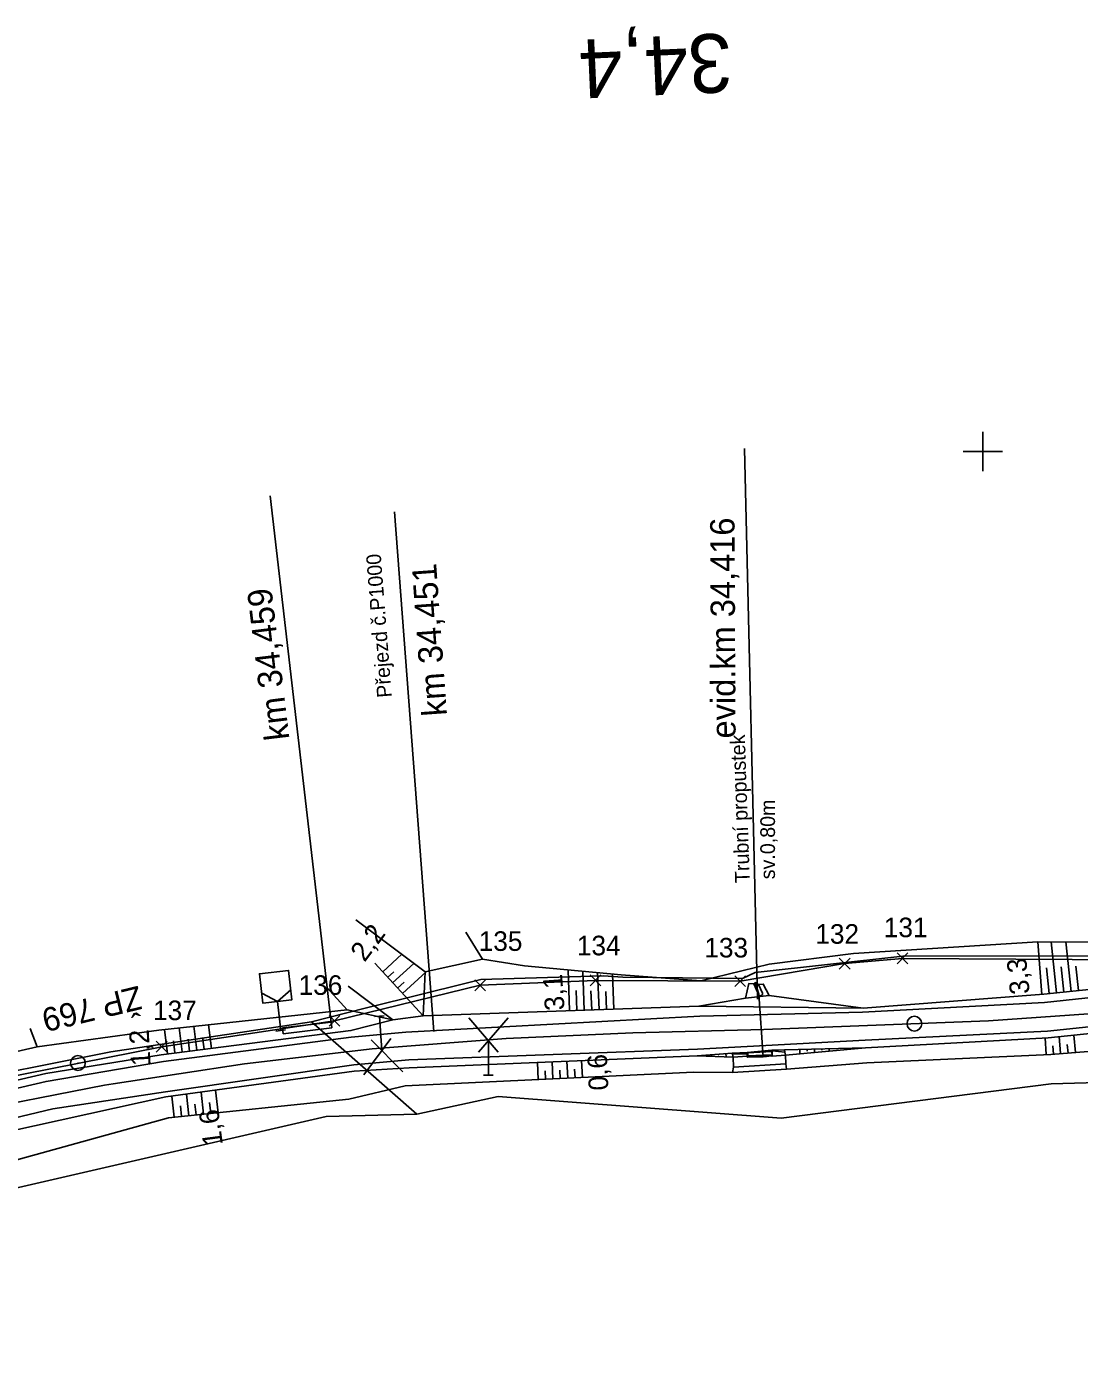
# Model space of a CAD drawing. Extents: x -805730 to -804640, y -1150889 to -1150366.
# Drawn here: x -805297.6 to -805190.1, y -1150691.7 to -1150556.6 of the extents above; entities that cross this region are included whole.
import ezdxf

# ---------------------------------------------------------------- set-up
doc = ezdxf.new("R2010")
doc.units = 0
for name, color, linetype in [('0381KM032-037P - Vrstva 1', 7, 'Continuous'), ('0381KM032-037P - Vrstva 17', 7, 'Continuous'), ('0381KM032-037P - Vrstva 19', 7, 'Continuous'), ('0381KM032-037P - Vrstva 4', 7, 'Continuous'), ('0381KM032-037P - Vrstva 48', 7, 'Continuous'), ('0381KM032-037P - Vrstva 49', 7, 'Continuous'), ('0381KM032-037P - Vrstva 51', 7, 'Continuous'), ('0381KM032-037P - Vrstva 55', 7, 'Continuous'), ('0381KM032-037P - Vrstva 7', 7, 'Continuous'), ('0381KM032-037P - Vrstva 9', 7, 'Continuous'), ('Default', 7, 'Continuous'), ('hran DP - hran DP', 7, 'Continuous'), ('krizky_1000 - Vrstva 1', 7, 'Continuous'), ('PSR_C2_2_Lomove_body_Vimperk - Vrstva 60', 7, 'Continuous'), ('PSR_C2_2_trasa_Vimperk - Kabelová trasa', 7, 'Continuous'), ('vyt_sit - ohrožené', 7, 'Continuous')]:
    doc.layers.add(name, color=color, linetype=linetype)

msp = doc.modelspace()

# ---------------------------------------------------------------- linework, layer by layer
at = {"layer": '0381KM032-037P - Vrstva 1'}
for points in [[(-805182.79, -1150656.72), (-805189.2, -1150657.4), (-805199.42, -1150658.12), (-805222.35, -1150659), (-805235.71, -1150659.34), (-805248.65, -1150659.92), (-805262.34, -1150660.99)], [(-805262.34, -1150660.99), (-805275.34, -1150662.5), (-805288.75, -1150664.54), (-805289.64, -1150664.68), (-805304.6, -1150667.62), (-805306.42, -1150668.06)]]:
    msp.add_lwpolyline(points, dxfattribs=at)
at = {"layer": '0381KM032-037P - Vrstva 17'}
for points in [[(-805070.8, -1150598.9), (-805121.06, -1150638.84), (-805152.76, -1150646.7), (-805170.92, -1150650.08), (-805194.39, -1150650.05), (-805213.2, -1150651.26), (-805221.79, -1150652.33), (-805228.79, -1150654.03)], [(-805228.79, -1150654.03), (-805236.91, -1150653.41), (-805246.77, -1150652.51), (-805251.08, -1150651.83), (-805252.77, -1150649.08)], [(-805266.94, -1150654.72), (-805264.88, -1150657), (-805284.09, -1150659.06), (-805296.52, -1150660.78), (-805297.22, -1150658.9)]]:
    msp.add_lwpolyline(points, dxfattribs=at)
at = {"layer": '0381KM032-037P - Vrstva 19'}
for p, q in [((-805224.33, -1150599.68), (-805223.01, -1150655.91)), ((-805222.9, -1150655.44), (-805223.36, -1150654.35)), ((-805222.89, -1150654.41), (-805222.49, -1150655.3)), ((-805223.99, -1150661.38), (-805221.54, -1150661.24)), ((-805221.51, -1150661.18), (-805221.49, -1150661.72)), ((-805225.47, -1150661.83), (-805224.04, -1150661.74)), ((-805224.04, -1150661.49), (-805224.04, -1150661.74)), ((-805221.51, -1150661.6), (-805224, -1150661.7)), ((-805224, -1150661.7), (-805224, -1150661.8)), ((-805224, -1150661.8), (-805221.51, -1150661.7)), ((-805221.51, -1150661.7), (-805221.51, -1150661.6))]:
    msp.add_line(p, q, dxfattribs=at)
msp.add_lwpolyline([(-805224.22, -1150655.82), (-805223.87, -1150654.3), (-805223.36, -1150654.35), (-805223.23, -1150654.21), (-805222.89, -1150654.41), (-805222.41, -1150654.36), (-805221.82, -1150655.55)], close=True, dxfattribs=at)
for points in [[(-805223.23, -1150654.21), (-805222.87, -1150655.41), (-805222.4, -1150661.78)], [(-805225.57, -1150661.42), (-805224.05, -1150661.35), (-805223.99, -1150661.38)], [(-805225.56, -1150661.53), (-805224.04, -1150661.49), (-805224.05, -1150661.35)], [(-805221.51, -1150661.7), (-805221.51, -1150661.69), (-805221.54, -1150661.24), (-805221.52, -1150661.12), (-805220.23, -1150661.07), (-805220.19, -1150661.33), (-805220.13, -1150661.62)], [(-805220.19, -1150661.33), (-805221.51, -1150661.18), (-805221.52, -1150661.12)], [(-805225.57, -1150661.42), (-805225.56, -1150661.53), (-805225.47, -1150661.83), (-805225.46, -1150662.84), (-805225.54, -1150663.4), (-805220.04, -1150663.05), (-805220.11, -1150662.52), (-805225.46, -1150662.84)], [(-805224, -1150661.7), (-805224.04, -1150661.74), (-805224.02, -1150661.84), (-805223.26, -1150661.81), (-805222.4, -1150661.78)], [(-805223.99, -1150661.81), (-805224, -1150661.8)], [(-805223.99, -1150661.38), (-805223.99, -1150661.81), (-805221.51, -1150661.69)], [(-805222.4, -1150661.78), (-805221.56, -1150661.7), (-805221.49, -1150661.72)], [(-805220.11, -1150662.52), (-805220.13, -1150661.62), (-805221.49, -1150661.72), (-805221.51, -1150661.6)]]:
    msp.add_lwpolyline(points, dxfattribs=at)
for centre, major_axis, ratio, start_param, end_param in [((-805222.69, -1150655.38), (0.215, 0.047), 0.800066, 3.235081, 6.495155), ((-805222.47, -1150661.77), (-0.4, -0.017), 0.197294, 3.17264, 6.315874), ((-805222.47, -1150661.77), (0.4, 0.019), 0.014453, 3.164337, 6.322931)]:
    msp.add_ellipse(centre, major_axis=major_axis, ratio=ratio, start_param=start_param, end_param=end_param, dxfattribs=at)
at = {"layer": '0381KM032-037P - Vrstva 4'}
for p, q in [((-805260.04, -1150606.16), (-805256.03, -1150659.22)), ((-805261.09, -1150657.61), (-805262.09, -1150657.68)), ((-805261.59, -1150657.65), (-805261.34, -1150661.14)), ((-805252.46, -1150657.82), (-805249.46, -1150661.32)), ((-805251.46, -1150661.32), (-805248.46, -1150657.82)), ((-805260.43, -1150659.92), (-805263.17, -1150663.62)), ((-805262.34, -1150660.99), (-805248.65, -1150659.92)), ((-805259.18, -1150663.34), (-805262.42, -1150660.06)), ((-805250.46, -1150663.67), (-805250.46, -1150660.17)), ((-805250.96, -1150663.67), (-805249.96, -1150663.67))]:
    msp.add_line(p, q, dxfattribs=at)
for points in [[(-805097.6, -1150634.39), (-805112.1, -1150639.75), (-805119.36, -1150642.27), (-805152.08, -1150650.89), (-805169.94, -1150653.7), (-805193.71, -1150656.24), (-805212.28, -1150657.22)], [(-805096.44, -1150637.01), (-805110.9, -1150642.46), (-805118.26, -1150644.98), (-805151.42, -1150653.61), (-805169.41, -1150656.67), (-805193.4, -1150659.17), (-805212.01, -1150660.08)], [(-805134.98, -1150644.55), (-805152.23, -1150649.93), (-805170.06, -1150652.94), (-805193.76, -1150655.4), (-805212.2, -1150656.84), (-805228.99, -1150656.61)], [(-805134.56, -1150650.98), (-805151.31, -1150654.12), (-805169.36, -1150657.36), (-805193.31, -1150659.84), (-805211.96, -1150660.88), (-805220.23, -1150661.07)], [(-805228.99, -1150656.61), (-805257.13, -1150657.62), (-805260.23, -1150658.03), (-805264.49, -1150659.11), (-805283.86, -1150661.58), (-805295.64, -1150663.5), (-805324.06, -1150670.09), (-805365.63, -1150680.4), (-805372.09, -1150681.89), (-805381.91, -1150683.24), (-805417.14, -1150687.42), (-805420, -1150686.97)], [(-805212.28, -1150657.22), (-805228.89, -1150657.63), (-805258.88, -1150659.27), (-805264.46, -1150659.8), (-805283.61, -1150662.28), (-805295.6, -1150664.3), (-805323.97, -1150670.91), (-805365.39, -1150681.52), (-805371.9, -1150683.14), (-805381.67, -1150685.01), (-805417.27, -1150688.09), (-805420, -1150686.97)], [(-805212.01, -1150660.08), (-805229.13, -1150661), (-805258.58, -1150662.1), (-805264.18, -1150662.62), (-805283.43, -1150665.36), (-805294.93, -1150667.11), (-805323.21, -1150673.86), (-805364.72, -1150684.28), (-805371.95, -1150685.67), (-805381.73, -1150687.49), (-805401.63, -1150689.36), (-805419.33, -1150691.07), (-805419.49, -1150691.68)], [(-805225.57, -1150661.42), (-805229.16, -1150661.68), (-805258.55, -1150662.93), (-805264.16, -1150663.27), (-805283.37, -1150665.88), (-805323.33, -1150674.68), (-805364.37, -1150685.33), (-805371.95, -1150687.26), (-805381.71, -1150688.97), (-805419.49, -1150691.68)]]:
    msp.add_lwpolyline(points, dxfattribs=at)
at = {"layer": '0381KM032-037P - Vrstva 48'}
for p, q in [((-805193.97, -1150655.42), (-805194.39, -1150650.05)), ((-805192.48, -1150655.27), (-805193.02, -1150650.05)), ((-805190.99, -1150655.11), (-805191.51, -1150650.05)), ((-805261.25, -1150653.12), (-805259.3, -1150651.33)), ((-805260.75, -1150653.68), (-805260.13, -1150653.11)), ((-805260.24, -1150654.23), (-805258.08, -1150652.25)), ((-805259.22, -1150655.33), (-805256.81, -1150653.11)), ((-805242.17, -1150657.08), (-805242.32, -1150652.92)), ((-805240.67, -1150657.03), (-805240.81, -1150653.06)), ((-805239.17, -1150656.98), (-805239.31, -1150653.2)), ((-805193.23, -1150655.34), (-805193.5, -1150652.7)), ((-805191.73, -1150655.19), (-805192, -1150652.62)), ((-805190.24, -1150655.03), (-805190.5, -1150652.54)), ((-805259.73, -1150654.78), (-805259.05, -1150654.16)), ((-805237.67, -1150656.92), (-805237.8, -1150653.33)), ((-805241.42, -1150657.06), (-805241.49, -1150655.02)), ((-805239.92, -1150657), (-805239.99, -1150655.06)), ((-805238.42, -1150656.95), (-805238.49, -1150655.11)), ((-805278.74, -1150660.93), (-805279.04, -1150658.52)), ((-805283.2, -1150661.49), (-805283.52, -1150659)), ((-805281.71, -1150661.3), (-805282.03, -1150658.84)), ((-805280.97, -1150661.21), (-805281.12, -1150659.98)), ((-805280.22, -1150661.11), (-805280.54, -1150658.68)), ((-805279.48, -1150661.02), (-805279.64, -1150659.81)), ((-805193.54, -1150661.57), (-805193.62, -1150659.86)), ((-805192.05, -1150661.47), (-805192.19, -1150659.72)), ((-805190.55, -1150661.35), (-805190.69, -1150659.57)), ((-805282.46, -1150661.4), (-805282.61, -1150660.16)), ((-805218.69, -1150661.03), (-805218.68, -1150661.49)), ((-805217.94, -1150661.02), (-805217.94, -1150661.22)), ((-805217.19, -1150661), (-805217.18, -1150661.35)), ((-805216.44, -1150660.98), (-805216.44, -1150661.13)), ((-805215.69, -1150660.96), (-805215.68, -1150661.22)), ((-805192.79, -1150661.53), (-805192.86, -1150660.66)), ((-805191.3, -1150661.41), (-805191.37, -1150660.53)), ((-805245.37, -1150664.11), (-805245.45, -1150662.37)), ((-805243.87, -1150664.03), (-805243.95, -1150662.31)), ((-805242.37, -1150663.96), (-805242.45, -1150662.25)), ((-805240.87, -1150663.89), (-805240.95, -1150662.18)), ((-805227.71, -1150661.57), (-805227.7, -1150661.74)), ((-805226.96, -1150661.52), (-805226.95, -1150661.64)), ((-805226.21, -1150661.47), (-805226.19, -1150661.8)), ((-805244.62, -1150664.07), (-805244.66, -1150663.21)), ((-805243.12, -1150664), (-805243.16, -1150663.14)), ((-805241.62, -1150663.93), (-805241.66, -1150663.07)), ((-805279.55, -1150667.65), (-805279.78, -1150665.39)), ((-805278.05, -1150667.5), (-805278.3, -1150665.19)), ((-805282.53, -1150667.97), (-805282.76, -1150665.8)), ((-805281.04, -1150667.81), (-805281.27, -1150665.6)), ((-805280.29, -1150667.73), (-805280.41, -1150666.61)), ((-805278.8, -1150667.58), (-805278.92, -1150666.44)), ((-805281.78, -1150667.89), (-805281.9, -1150666.79))]:
    msp.add_line(p, q, dxfattribs=at)
at = {"layer": '0381KM032-037P - Vrstva 49'}
for p, q in [((-805257.13, -1150657.62), (-805262.06, -1150652.24)), ((-805256.9, -1150653.13), (-805257.13, -1150657.62)), ((-805220.23, -1150661.07), (-805211.96, -1150660.88)), ((-805224.04, -1150661.74), (-805225.47, -1150661.83))]:
    msp.add_line(p, q, dxfattribs=at)
for points in [[(-805070.8, -1150598.9), (-805121.06, -1150638.84), (-805152.76, -1150646.7), (-805170.92, -1150650.08), (-805194.39, -1150650.05), (-805213.2, -1150651.26), (-805221.79, -1150652.33), (-805228.79, -1150654.03)], [(-805134.98, -1150644.55), (-805152.23, -1150649.93), (-805170.06, -1150652.94), (-805193.76, -1150655.4), (-805212.2, -1150656.84), (-805221.82, -1150655.55)], [(-805228.79, -1150654.03), (-805236.91, -1150653.41), (-805246.77, -1150652.51), (-805251.08, -1150651.83), (-805256.9, -1150653.13), (-805263.99, -1150647.81)], [(-805134.43, -1150652.2), (-805150.83, -1150656.03), (-805168.82, -1150659.61), (-805193.05, -1150661.55), (-805211.83, -1150662.42), (-805220.04, -1150663.05)], [(-805151.31, -1150654.12), (-805169.36, -1150657.36), (-805193.31, -1150659.84), (-805211.96, -1150660.88), (-805220.13, -1150661.62)], [(-805221.82, -1150655.55), (-805224.22, -1150655.82), (-805228.99, -1150656.61), (-805257.13, -1150657.62)], [(-805296.52, -1150660.78), (-805284.09, -1150659.06), (-805264.88, -1150657), (-805260.23, -1150658.03)], [(-805257.13, -1150657.62), (-805260.23, -1150658.03), (-805264.49, -1150659.11)], [(-805420, -1150686.97), (-805417.14, -1150687.42), (-805381.91, -1150683.24), (-805372.09, -1150681.89), (-805365.63, -1150680.4), (-805324.06, -1150670.09), (-805295.64, -1150663.5), (-805283.86, -1150661.58), (-805264.49, -1150659.11)], [(-805296.52, -1150660.78), (-805324.89, -1150667.28), (-805344.39, -1150673.21)], [(-805220.23, -1150661.07), (-805221.52, -1150661.12), (-805224.05, -1150661.35), (-805225.57, -1150661.42), (-805229.16, -1150661.68)], [(-805372.13, -1150688.5), (-805323.33, -1150674.68), (-805283.37, -1150665.88), (-805264.16, -1150663.27), (-805258.55, -1150662.93), (-805229.16, -1150661.68), (-805225.47, -1150661.83)], [(-805224.04, -1150661.74), (-805224.02, -1150661.84), (-805223.26, -1150661.81), (-805222.4, -1150661.78), (-805221.56, -1150661.7)], [(-805221.56, -1150661.7), (-805221.49, -1150661.72), (-805220.13, -1150661.62)], [(-805229.52, -1150663.36), (-805258.94, -1150664.75), (-805264.69, -1150666.1), (-805283.13, -1150668.03), (-805332.88, -1150681.81), (-805363.18, -1150690.85)], [(-805229.52, -1150663.36), (-805225.54, -1150663.4), (-805220.04, -1150663.05)]]:
    msp.add_lwpolyline(points, dxfattribs=at)
at = {"layer": '0381KM032-037P - Vrstva 51'}
msp.add_line((-805264.77, -1150654.58), (-805260.23, -1150658.03), dxfattribs=at)
msp.add_lwpolyline([(-805262.06, -1150652.24), (-805257.13, -1150657.62), (-805260.23, -1150658.03)], dxfattribs=at)
at = {"layer": '0381KM032-037P - Vrstva 55'}
msp.add_line((-805268.53, -1150658.22), (-805257.77, -1150667.64), dxfattribs=at)
at = {"layer": '0381KM032-037P - Vrstva 7'}
for p, q in [((-805272, -1150656.13), (-805271.65, -1150659.11)), ((-805272.15, -1150659.17), (-805271.16, -1150659.05))]:
    msp.add_line(p, q, dxfattribs=at)
for points in [[(-805272, -1150656.13), (-805270.51, -1150655.96), (-805270.85, -1150652.98), (-805273.83, -1150653.32), (-805273.49, -1150656.3), (-805272, -1150656.13)], [(-805273.6, -1150655.31), (-805272, -1150656.13), (-805270.62, -1150654.96)]]:
    msp.add_lwpolyline(points, dxfattribs=at)
msp.add_circle((-805206.98, -1150658.41), 0.75, dxfattribs=at)
at = {"layer": '0381KM032-037P - Vrstva 9'}
for p, q in [((-805266.48, -1150658.55), (-805272.73, -1150604.53)), ((-805266.52, -1150658.25), (-805271.48, -1150658.85)), ((-805266.52, -1150658.25), (-805266.59, -1150657.67)), ((-805266.45, -1150658.84), (-805266.52, -1150658.25)), ((-805271.48, -1150658.85), (-805271.41, -1150659.44)), ((-805271.41, -1150659.44), (-805266.45, -1150658.84))]:
    msp.add_line(p, q, dxfattribs=at)
at = {"layer": 'hran DP - hran DP'}
for p, q in [((-805223.22, -1150653.17), (-805208.17, -1150651.53)), ((-805208.17, -1150651.53), (-805178.93, -1150651.45)), ((-805224.51, -1150653.79), (-805223.22, -1150653.17)), ((-805259.03, -1150655.84), (-805251.25, -1150653.89)), ((-805251.25, -1150653.89), (-805238.75, -1150653.54)), ((-805238.75, -1150653.54), (-805236.73, -1150653.66)), ((-805236.73, -1150653.66), (-805224.51, -1150653.79)), ((-805263.04, -1150656.84), (-805259.03, -1150655.84)), ((-805268.53, -1150658.22), (-805263.04, -1150656.84)), ((-805288.99, -1150661.29), (-805268.53, -1150658.22)), ((-805313.93, -1150666.21), (-805288.99, -1150661.29)), ((-805161.69, -1150663.73), (-805193.03, -1150664.54)), ((-805193.03, -1150664.54), (-805220.59, -1150668.04)), ((-805249.45, -1150665.86), (-805257.77, -1150667.64)), ((-805220.59, -1150668.04), (-805249.45, -1150665.86)), ((-805267.02, -1150667.87), (-805308.19, -1150677.39)), ((-805257.77, -1150667.64), (-805267.02, -1150667.87))]:
    msp.add_line(p, q, dxfattribs=at)
at = {"layer": 'krizky_1000 - Vrstva 1'}
for points in [[(-805200, -1150598), (-805200, -1150602)], [(-805202, -1150600), (-805198, -1150600)]]:
    msp.add_lwpolyline(points, dxfattribs=at)
at = {"layer": 'PSR_C2_2_Lomove_body_Vimperk - Vrstva 60'}
for p, q in [((-805214.65, -1150652.83), (-805213.55, -1150651.73)), ((-805213.55, -1150652.83), (-805214.65, -1150651.73)), ((-805208.74, -1150652.29), (-805207.64, -1150651.19)), ((-805207.64, -1150652.29), (-805208.74, -1150651.19)), ((-805251.84, -1150655.04), (-805250.74, -1150653.94)), ((-805250.74, -1150655.04), (-805251.84, -1150653.94)), ((-805240.07, -1150654.54), (-805238.97, -1150653.44)), ((-805238.97, -1150654.54), (-805240.07, -1150653.44)), ((-805225.31, -1150654.62), (-805224.21, -1150653.52)), ((-805224.21, -1150654.62), (-805225.31, -1150653.52)), ((-805266.72, -1150658.66), (-805265.62, -1150657.56)), ((-805265.62, -1150658.66), (-805266.72, -1150657.56)), ((-805284.36, -1150661.31), (-805283.26, -1150660.21)), ((-805283.26, -1150661.31), (-805284.36, -1150660.21))]:
    msp.add_line(p, q, dxfattribs=at)
at = {"layer": 'PSR_C2_2_trasa_Vimperk - Kabelová trasa'}
for points in [[(-805214.1, -1150652.28), (-805208.19, -1150651.74), (-805179.31, -1150651.91), (-805164.88, -1150649.95), (-805150.36, -1150646.9), (-805138.79, -1150644.66), (-805134.9, -1150644.97), (-805132.95, -1150644.53), (-805122.45, -1150641.59)], [(-805239.52, -1150653.99), (-805224.76, -1150654.07), (-805214.1, -1150652.28)], [(-805372.22, -1150682.03), (-805349.68, -1150676.27), (-805317.98, -1150667.75), (-805311.89, -1150666.33), (-805283.81, -1150660.76), (-805266.17, -1150658.11), (-805251.29, -1150654.49), (-805239.52, -1150653.99)]]:
    msp.add_lwpolyline(points, dxfattribs=at)
at = {"layer": 'vyt_sit - ohrožené'}
msp.add_line((-805292.41, -1150662.43), (-805292.31, -1150662.43), dxfattribs=at)
msp.add_circle((-805292.36, -1150662.43), 0.756, dxfattribs=at)

# ---------------------------------------------------------------- texts
at = {"layer": '0381KM032-037P - Vrstva 19'}
for s, height, rotation, p in [('evid.km 34,416', 2.4868, 90.2833, (-805225.23, -1150629.29)), ('Trubní propustek', 1.4998, 91.9626, (-805223.77, -1150644.03)), ('sv.0,80m', 1.5, 89.9669, (-805221.21, -1150643.67))]:
    msp.add_text(s, height=height, rotation=rotation, dxfattribs=at).set_placement(p)
at = {"layer": '0381KM032-037P - Vrstva 4'}
for s, height, rotation, p in [('Přejezd č.P1000', 1.5, 94.4666, (-805260.31, -1150625.07)), ('km 34,451', 2.5, 94.1036, (-805254.68, -1150626.93))]:
    msp.add_text(s, height=height, rotation=rotation, dxfattribs=at).set_placement(p)
at = {"layer": '0381KM032-037P - Vrstva 48'}
for s, rotation, p in [('2,2', 53.0616, (-805263.1, -1150652.2)), ('3,3', 95.9333, (-805195.2, -1150655.32)), ('3,1', 94.1143, (-805242.68, -1150657)), ('1,2', 93.2392, (-805284.93, -1150662.67)), ('0,6', 92.4516, (-805238.21, -1150665.19)), ('1,6', 97.414, (-805277.56, -1150670.74))]:
    msp.add_text(s, height=2, rotation=rotation, dxfattribs=at).set_placement(p)
at = {"layer": '0381KM032-037P - Vrstva 7'}
msp.add_text('34,4', height=6, rotation=182.5512, dxfattribs=at).set_placement((-805225.74, -1150557.29))
at = {"layer": '0381KM032-037P - Vrstva 9'}
msp.add_text('km 34,459', height=2.5, rotation=96.8511, dxfattribs=at).set_placement((-805270.76, -1150629.34))
at = {"layer": 'Default'}
for s, p in [('131', (-805210.1, -1150649.58)), ('135', (-805251.45, -1150650.98)), ('132', (-805217.09, -1150650.25)), ('134', (-805241.43, -1150651.43)), ('133', (-805228.42, -1150651.65)), ('136', (-805269.83, -1150655.47)), ('137', (-805284.69, -1150658.05))]:
    msp.add_text(s, height=2, dxfattribs=at).set_placement(p)
at = {"layer": 'vyt_sit - ohrožené'}
msp.add_text('ŽP 769', height=2.4, rotation=193.6062, dxfattribs=at).set_placement((-805286.16, -1150654.52))

doc.saveas('drawing.dxf')
